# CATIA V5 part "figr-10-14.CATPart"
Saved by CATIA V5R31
Part number: Part1
Bounding box of the stored display mesh (mm): x 0 to 0, y 0 to 59.085, z 0 to 150
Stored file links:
  D:\PROJECTS\Project 2021\US EDITION\CATIA V5 6R 2021\Resources\Part Files\c10_catia_v5_6r2021_prt\c10_catia_v5_6r2021_prt\figr-10-14.CATPart
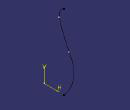
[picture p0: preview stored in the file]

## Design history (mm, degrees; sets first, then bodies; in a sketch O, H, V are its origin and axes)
Set1
  Sketch1 on yz-plane, origin (0, 0, 0), H (0, 1, 0), V (0, 0, 1)
    arc A1 centre (219.5293, 176.8574) radius 194.8379 from (50.3627, 80.1907) to (30.3627, 130.1907) cw
    arc A2 centre (-7.8186, 46.9443) radius 67.0103 from (50.3627, 80.1907) to (40, 0) cw
    arc A3 centre (47.0688, 134.312) radius 17.207 from (30.3627, 130.1907) to (40, 150) cw
    axis line L1 (0, 156.5671) -> (0, -24.1442)
    vertical: L1 V
  Revol1: Element1 Sketch1, Angle1 -60
Body1 (main body)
